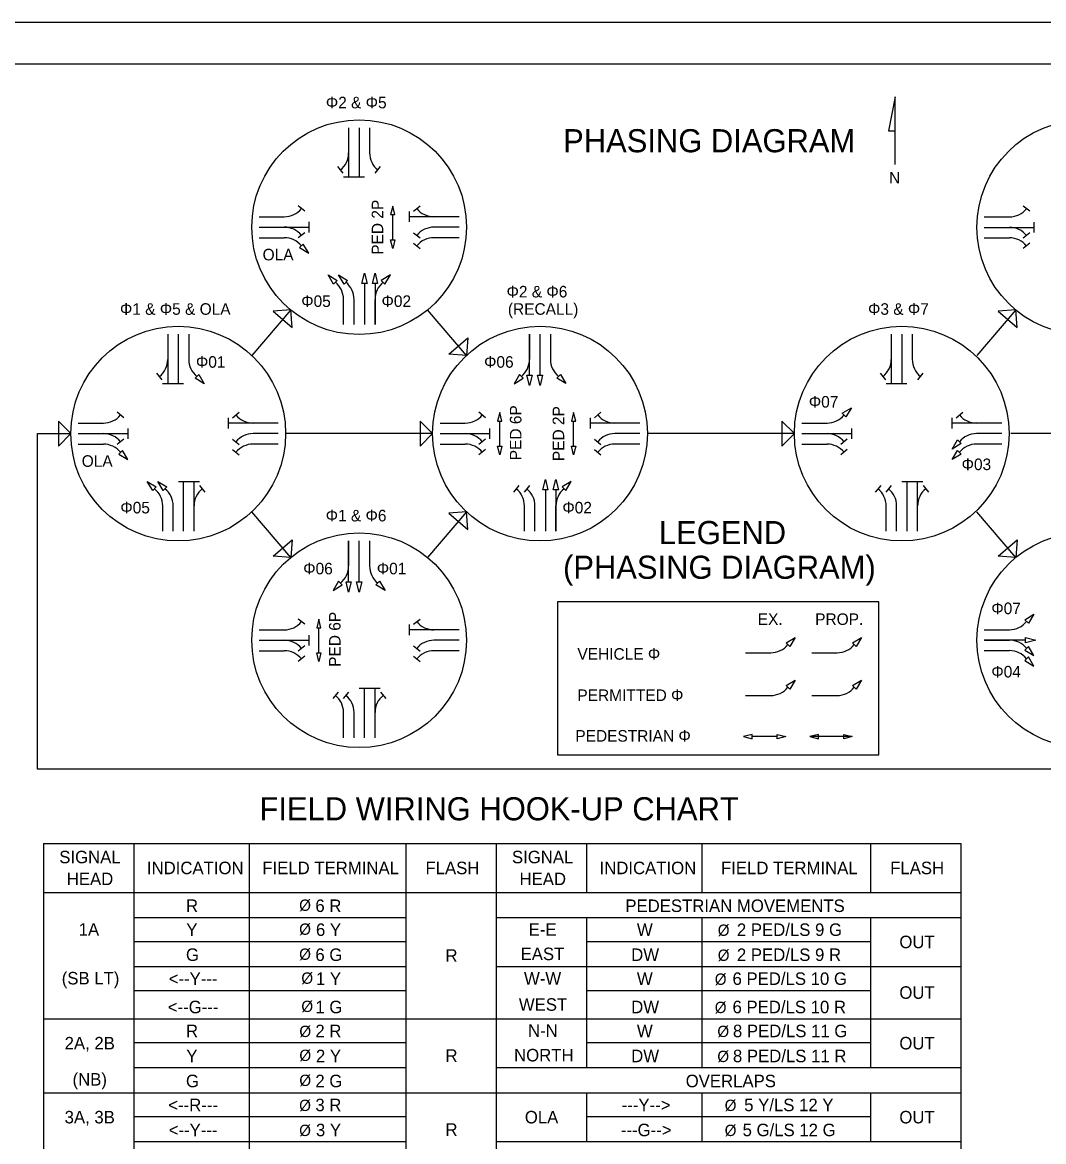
# Model space of a CAD drawing. Extents: x 0 to 34, y 0 to 22.
# Drawn here: x 14.75 to 27.11, y 8.45 to 22 of the extents above; entities that cross this region are included whole.
import ezdxf

# ---------------------------------------------------------------- set-up
doc = ezdxf.new("R2010")
doc.units = 0
for name, color, linetype in [('SG_P_Text', 7, 'Continuous'), ('SH_Border', 7, 'Continuous'), ('SH_Cut_Line', 7, 'Continuous'), ('SH_Text', 7, 'Continuous')]:
    doc.layers.add(name, color=color, linetype=linetype)

msp = doc.modelspace()

# ---------------------------------------------------------------- linework, layer by layer
at = {"layer": 'SG_P_Text'}
for p, q in [((18.699, 20.725), (18.699, 20.124)), ((18.699, 20.725), (18.699, 20.419)), ((18.826, 20.725), (18.826, 20.124)), ((18.952, 20.725), (18.952, 20.42)), ((18.632, 20.173), (18.568, 20.253)), ((19.019, 20.173), (19.083, 20.253)), ((18.762, 20.124), (18.635, 20.124)), ((18.889, 20.124), (18.762, 20.124)), ((18.167, 19.713), (18.087, 19.777)), ((19.233, 19.367), (19.233, 19.672)), ((19.436, 19.583), (19.436, 19.71)), ((19.484, 19.713), (19.564, 19.777)), ((26.947, 19.712), (26.868, 19.776)), ((17.615, 19.646), (17.92, 19.646)), ((17.615, 19.52), (18.215, 19.52)), ((17.615, 19.52), (17.92, 19.52)), ((18.215, 19.583), (18.215, 19.456)), ((20.036, 19.646), (19.436, 19.646)), ((20.036, 19.646), (19.731, 19.646)), ((20.036, 19.52), (19.731, 19.52)), ((26.395, 19.645), (26.701, 19.645)), ((26.395, 19.518), (26.996, 19.518)), ((26.395, 19.518), (26.701, 19.518)), ((26.996, 19.582), (26.996, 19.455)), ((17.615, 19.393), (17.92, 19.393)), ((18.167, 19.453), (18.087, 19.389)), ((19.484, 19.453), (19.564, 19.389)), ((20.036, 19.393), (19.731, 19.393)), ((26.395, 19.392), (26.701, 19.392)), ((26.947, 19.451), (26.868, 19.387)), ((19.484, 19.326), (19.564, 19.262)), ((26.947, 19.325), (26.868, 19.261)), ((18.891, 18.838), (18.891, 18.34)), ((19.018, 18.838), (19.018, 18.34)), ((18.637, 18.34), (18.637, 18.646)), ((18.764, 18.34), (18.764, 18.646)), ((19.018, 18.34), (19.018, 18.646)), ((17.997, 18.518), (17.526, 17.966)), ((20.125, 17.967), (19.654, 18.519)), ((26.777, 18.518), (26.307, 17.967)), ((16.509, 18.225), (16.509, 17.624)), ((16.509, 18.225), (16.509, 17.919)), ((16.635, 18.225), (16.635, 17.624)), ((16.762, 18.225), (16.762, 17.919)), ((20.889, 17.727), (20.889, 18.225)), ((20.889, 18.225), (20.889, 17.919)), ((21.016, 17.727), (21.016, 18.225)), ((21.142, 18.225), (21.142, 17.92)), ((25.269, 18.225), (25.269, 17.624)), ((25.269, 18.225), (25.269, 17.919)), ((25.396, 18.225), (25.396, 17.624)), ((25.523, 18.225), (25.523, 17.92)), ((16.442, 17.673), (16.378, 17.753)), ((16.572, 17.624), (16.445, 17.624)), ((16.699, 17.624), (16.572, 17.624)), ((25.202, 17.673), (25.138, 17.753)), ((25.332, 17.624), (25.206, 17.624)), ((25.459, 17.624), (25.332, 17.624)), ((25.59, 17.673), (25.654, 17.753)), ((15.977, 17.213), (15.897, 17.278)), ((17.294, 17.213), (17.374, 17.278)), ((20.357, 17.213), (20.277, 17.278)), ((21.674, 17.213), (21.754, 17.278)), ((26.055, 17.213), (26.134, 17.278)), ((15.425, 17.147), (15.73, 17.147)), ((16.025, 17.083), (16.025, 16.956)), ((17.245, 17.083), (17.245, 17.21)), ((17.846, 17.147), (17.245, 17.147)), ((17.846, 17.147), (17.541, 17.147)), ((19.805, 17.147), (20.111, 17.147)), ((20.406, 17.083), (20.406, 16.956)), ((20.528, 16.867), (20.528, 17.172)), ((21.423, 16.867), (21.423, 17.172)), ((21.626, 17.083), (21.626, 17.21)), ((22.226, 17.147), (21.626, 17.147)), ((22.226, 17.147), (21.921, 17.147)), ((24.185, 17.147), (24.491, 17.147)), ((24.786, 17.083), (24.786, 16.956)), ((26.006, 17.083), (26.006, 17.21)), ((26.606, 17.147), (26.006, 17.147)), ((26.606, 17.147), (26.301, 17.147)), ((15.425, 17.02), (16.025, 17.02)), ((15.425, 17.02), (15.73, 17.02)), ((15.977, 16.953), (15.897, 16.889)), ((17.294, 16.953), (17.374, 16.889)), ((17.846, 17.02), (17.541, 17.02)), ((19.716, 17.02), (17.935, 17.02)), ((19.805, 17.02), (20.406, 17.02)), ((19.805, 17.02), (20.111, 17.02)), ((20.357, 16.953), (20.277, 16.889)), ((21.674, 16.953), (21.754, 16.889)), ((22.226, 17.02), (21.921, 17.02)), ((24.096, 17.02), (22.315, 17.02)), ((24.185, 17.02), (24.786, 17.02)), ((24.185, 17.02), (24.491, 17.02)), ((24.737, 16.953), (24.657, 16.889)), ((26.606, 17.02), (26.301, 17.02)), ((28.496, 17.02), (26.716, 17.02)), ((15.425, 16.893), (15.73, 16.893)), ((17.294, 16.826), (17.374, 16.762)), ((17.846, 16.893), (17.541, 16.893)), ((19.805, 16.893), (20.111, 16.893)), ((20.357, 16.826), (20.277, 16.762)), ((21.674, 16.826), (21.754, 16.762)), ((22.226, 16.893), (21.921, 16.893)), ((24.185, 16.893), (24.491, 16.893)), ((24.737, 16.826), (24.657, 16.762)), ((26.606, 16.893), (26.301, 16.893)), ((16.637, 16.441), (16.764, 16.441)), ((16.701, 15.84), (16.701, 16.441)), ((16.764, 16.441), (16.891, 16.441)), ((16.827, 15.84), (16.827, 16.441)), ((25.398, 16.441), (25.525, 16.441)), ((25.461, 15.84), (25.461, 16.441)), ((25.525, 16.441), (25.651, 16.441)), ((25.588, 15.84), (25.588, 16.441)), ((16.894, 16.392), (16.958, 16.313)), ((20.76, 16.392), (20.696, 16.313)), ((20.887, 16.392), (20.823, 16.313)), ((21.081, 16.338), (21.081, 15.84)), ((21.208, 16.338), (21.208, 15.84)), ((25.141, 16.392), (25.076, 16.313)), ((25.267, 16.392), (25.203, 16.313)), ((25.655, 16.392), (25.719, 16.313)), ((16.447, 15.84), (16.447, 16.146)), ((16.574, 15.84), (16.574, 16.146)), ((16.827, 15.84), (16.827, 16.146)), ((20.827, 15.84), (20.827, 16.146)), ((20.954, 15.84), (20.954, 16.146)), ((21.208, 15.84), (21.208, 16.146)), ((25.207, 15.84), (25.207, 16.146)), ((25.334, 15.84), (25.334, 16.146)), ((25.588, 15.84), (25.588, 16.146)), ((17.998, 15.52), (17.526, 16.073)), ((20.125, 16.073), (19.653, 15.52)), ((26.778, 15.521), (26.307, 16.072)), ((18.699, 15.225), (18.699, 15.723)), ((18.699, 15.723), (18.699, 15.417)), ((18.826, 15.225), (18.826, 15.723)), ((18.952, 15.723), (18.952, 15.417)), ((18.167, 14.711), (18.087, 14.775)), ((19.484, 14.711), (19.564, 14.775)), ((17.615, 14.644), (17.92, 14.644)), ((18.338, 14.365), (18.338, 14.67)), ((19.436, 14.581), (19.436, 14.708)), ((20.036, 14.644), (19.436, 14.644)), ((20.036, 14.644), (19.731, 14.644)), ((26.395, 14.646), (26.701, 14.646)), ((17.615, 14.518), (18.215, 14.518)), ((17.615, 14.518), (17.92, 14.518)), ((18.215, 14.581), (18.215, 14.454)), ((20.036, 14.518), (19.731, 14.518)), ((26.893, 14.519), (26.395, 14.519)), ((26.396, 14.519), (26.701, 14.519)), ((17.615, 14.391), (17.92, 14.391)), ((18.167, 14.451), (18.087, 14.387)), ((19.484, 14.451), (19.564, 14.387)), ((20.036, 14.391), (19.731, 14.391)), ((26.395, 14.392), (26.701, 14.392)), ((18.167, 14.324), (18.087, 14.26)), ((19.484, 14.324), (19.564, 14.26)), ((23.505, 14.366), (23.81, 14.366)), ((24.308, 14.366), (24.614, 14.366)), ((18.57, 13.89), (18.506, 13.811)), ((18.697, 13.89), (18.633, 13.811)), ((18.827, 13.939), (18.954, 13.939)), ((18.891, 13.338), (18.891, 13.939)), ((18.954, 13.939), (19.081, 13.939)), ((19.018, 13.338), (19.018, 13.939)), ((19.085, 13.89), (19.149, 13.811)), ((23.505, 13.849), (23.81, 13.849)), ((24.308, 13.849), (24.614, 13.849)), ((18.637, 13.338), (18.637, 13.644)), ((18.764, 13.338), (18.764, 13.644)), ((19.018, 13.338), (19.018, 13.644)), ((23.889, 13.351), (23.584, 13.351)), ((24.797, 13.351), (24.284, 13.351))]:
    msp.add_line(p, q, dxfattribs=at)
for points in [[(19.259, 19.672), (19.233, 19.776), (19.207, 19.672)], [(18.105, 19.272), (18.215, 19.206), (18.149, 19.316)], [(19.259, 19.367), (19.233, 19.263), (19.207, 19.367)], [(18.516, 18.83), (18.45, 18.941), (18.56, 18.874)], [(18.643, 18.83), (18.577, 18.941), (18.687, 18.874)], [(18.859, 18.838), (18.891, 18.963), (18.922, 18.838)], [(18.986, 18.838), (19.018, 18.963), (19.049, 18.838)], [(19.139, 18.83), (19.205, 18.941), (19.094, 18.874)], [(17.997, 18.518), (17.783, 18.502), (18.014, 18.305)], [(26.777, 18.518), (26.563, 18.501), (26.793, 18.304)], [(20.125, 17.967), (19.912, 17.983), (20.142, 18.18)], [(16.883, 17.735), (16.949, 17.624), (16.839, 17.691)], [(20.768, 17.735), (20.702, 17.624), (20.812, 17.691)], [(20.92, 17.727), (20.889, 17.602), (20.858, 17.727)], [(21.047, 17.727), (21.016, 17.602), (20.984, 17.727)], [(21.263, 17.735), (21.33, 17.625), (21.219, 17.691)], [(20.554, 17.172), (20.528, 17.276), (20.502, 17.172)], [(21.449, 17.172), (21.423, 17.276), (21.397, 17.172)], [(24.675, 17.268), (24.786, 17.334), (24.719, 17.223)], [(15.336, 17.02), (15.184, 17.171), (15.184, 16.868)], [(19.716, 17.02), (19.565, 17.171), (19.564, 16.868)], [(24.096, 17.02), (23.945, 17.171), (23.945, 16.868)], [(26.117, 16.899), (26.006, 16.833), (26.072, 16.943)], [(15.915, 16.772), (16.025, 16.706), (15.959, 16.816)], [(20.554, 16.867), (20.528, 16.763), (20.502, 16.867)], [(21.449, 16.867), (21.423, 16.763), (21.397, 16.867)], [(26.117, 16.772), (26.006, 16.706), (26.072, 16.816)], [(16.326, 16.33), (16.26, 16.441), (16.37, 16.375)], [(16.453, 16.33), (16.387, 16.441), (16.497, 16.375)], [(21.05, 16.338), (21.081, 16.463), (21.112, 16.338)], [(21.176, 16.338), (21.208, 16.463), (21.239, 16.338)], [(21.329, 16.33), (21.395, 16.441), (21.284, 16.375)], [(20.125, 16.073), (19.912, 16.056), (20.142, 15.859)], [(17.998, 15.52), (17.784, 15.536), (18.015, 15.733)], [(26.778, 15.521), (26.564, 15.537), (26.795, 15.734)], [(18.578, 15.233), (18.512, 15.122), (18.622, 15.189)], [(18.73, 15.225), (18.699, 15.1), (18.667, 15.225)], [(18.857, 15.225), (18.826, 15.1), (18.794, 15.225)], [(19.073, 15.233), (19.14, 15.122), (19.029, 15.189)], [(25.12, 14.982), (21.228, 14.982), (21.228, 13.129), (25.12, 13.129)], [(18.364, 14.67), (18.338, 14.774), (18.312, 14.67)], [(26.885, 14.767), (26.996, 14.833), (26.929, 14.723)], [(23.995, 14.487), (24.105, 14.553), (24.039, 14.443)], [(24.798, 14.487), (24.909, 14.553), (24.843, 14.443)], [(26.893, 14.55), (27.018, 14.519), (26.893, 14.488)], [(26.886, 14.398), (26.996, 14.332), (26.93, 14.442)], [(18.364, 14.365), (18.338, 14.261), (18.312, 14.365)], [(26.885, 14.271), (26.996, 14.205), (26.93, 14.316)], [(23.995, 13.97), (24.105, 14.036), (24.039, 13.926)], [(24.798, 13.97), (24.909, 14.036), (24.843, 13.926)], [(23.584, 13.377), (23.48, 13.351), (23.584, 13.325)], [(23.889, 13.377), (23.994, 13.351), (23.889, 13.325)], [(24.388, 13.377), (24.284, 13.351), (24.388, 13.325)], [(24.693, 13.377), (24.797, 13.351), (24.693, 13.325)]]:
    msp.add_lwpolyline(points, close=True, dxfattribs=at)
msp.add_lwpolyline([(31.096, 17.02), (31.502, 17.02), (31.502, 12.958), (15.336, 12.958), (14.93, 12.958), (14.93, 17.02), (15.336, 17.02)], dxfattribs=at)
for centre in [(18.826, 19.52), (27.606, 19.518), (16.635, 17.02), (21.016, 17.02), (25.396, 17.02), (18.826, 14.518), (27.606, 14.519)]:
    msp.add_circle(centre, 1.3, dxfattribs=at)
for centre, start, end in [((18.434, 20.419), 308.7993, 0), ((19.217, 20.42), 180, 231.2007), ((17.92, 19.911), 270, 321.2007), ((19.731, 19.911), 218.7993, 270), ((26.701, 19.91), 270, 321.2007), ((17.92, 19.255), 38.7993, 90), ((19.731, 19.255), 90, 141.2007), ((26.701, 19.253), 38.7993, 90), ((17.92, 19.128), 38.7993, 90), ((19.731, 19.128), 90, 141.2007), ((26.701, 19.126), 38.7993, 90), ((18.372, 18.646), 360, 51.2007), ((18.499, 18.646), 360, 51.2007), ((19.283, 18.646), 128.8122, 180.0129), ((16.244, 17.919), 308.7993, 0), ((17.027, 17.919), 180, 231.2007), ((20.624, 17.919), 308.8122, 0.0129), ((21.407, 17.92), 179.9871, 231.1878), ((25.004, 17.919), 308.7993, 0), ((25.788, 17.92), 180, 231.2007), ((15.73, 17.412), 270, 321.2007), ((17.541, 17.412), 218.7993, 270), ((20.111, 17.412), 270, 321.2007), ((21.921, 17.412), 218.7993, 270), ((24.491, 17.412), 270, 321.2007), ((26.301, 17.412), 218.7993, 270), ((15.73, 16.755), 38.7993, 90), ((17.541, 16.755), 90, 141.2007), ((20.111, 16.755), 38.7993, 90), ((21.921, 16.755), 90, 141.2007), ((24.491, 16.755), 38.7993, 90), ((26.301, 16.755), 90, 141.2007), ((15.73, 16.628), 38.7993, 90), ((17.541, 16.628), 90, 141.2007), ((20.111, 16.628), 38.7993, 90), ((21.921, 16.628), 90, 141.2007), ((24.491, 16.628), 38.7993, 90), ((26.301, 16.628), 90, 141.2007), ((16.182, 16.146), 360, 51.2007), ((16.309, 16.146), 360, 51.2007), ((17.092, 16.146), 128.7993, 180), ((20.562, 16.146), 360, 51.2007), ((20.689, 16.146), 360, 51.2007), ((21.473, 16.146), 128.8122, 180.0129), ((24.942, 16.146), 360, 51.2007), ((25.069, 16.146), 360, 51.2007), ((25.853, 16.146), 128.7993, 180), ((18.434, 15.417), 308.8122, 0.0129), ((19.217, 15.417), 180, 231.2007), ((17.92, 14.909), 270, 321.2007), ((19.731, 14.909), 218.7993, 270), ((26.701, 14.911), 270, 321.2007), ((17.92, 14.253), 38.7993, 90), ((19.731, 14.253), 90, 141.2007), ((26.701, 14.254), 38.8122, 90.0129), ((17.92, 14.126), 38.7993, 90), ((19.731, 14.126), 90, 141.2007), ((23.81, 14.631), 270.0129, 321.2136), ((24.614, 14.631), 270.0129, 321.2136), ((26.701, 14.127), 38.8122, 90.0129), ((18.372, 13.644), 360, 51.2007), ((18.499, 13.644), 360, 51.2007), ((19.283, 13.644), 128.7993, 180), ((23.81, 14.114), 270, 321.2007), ((24.614, 14.114), 270, 321.2007)]:
    msp.add_arc(centre, 0.265, start, end, dxfattribs=at)
at = {"layer": 'SH_Border'}
msp.add_lwpolyline([(1.5, 21.5), (33.5, 21.5), (33.5, 0.5), (1.5, 0.5)], close=True, dxfattribs=at)
at = {"layer": 'SH_Cut_Line'}
msp.add_lwpolyline([(0, 0), (34, 0), (34, 22), (0, 22)], close=True, dxfattribs=at)
at = {"layer": 'SH_Text'}
for p, q in [((25.317, 20.278), (25.317, 21.098)), ((15.005, 12.057), (20.486, 12.057)), ((15.005, 12.057), (15.005, 11.161)), ((16.099, 12.057), (16.099, 11.161)), ((17.495, 12.057), (17.495, 11.161)), ((19.393, 12.057), (19.393, 11.161)), ((20.486, 12.057), (26.113, 12.057)), ((20.486, 12.057), (20.486, 11.161)), ((21.58, 12.057), (21.58, 11.464)), ((22.977, 12.057), (22.977, 11.464)), ((25.019, 12.057), (25.019, 11.464)), ((26.113, 12.057), (26.113, 11.161)), ((15.005, 11.464), (20.486, 11.464)), ((20.486, 11.464), (26.113, 11.464)), ((15.005, 11.161), (15.005, 9.039)), ((16.099, 11.161), (19.393, 11.161)), ((16.099, 11.161), (16.099, 9.039)), ((17.495, 11.161), (17.495, 9.039)), ((19.393, 11.161), (19.393, 9.039)), ((20.486, 11.161), (26.113, 11.161)), ((20.486, 11.161), (20.486, 9.039)), ((21.58, 11.161), (21.58, 9.342)), ((22.977, 11.161), (22.977, 9.342)), ((25.019, 11.161), (25.019, 9.342)), ((26.113, 11.161), (26.113, 9.039)), ((16.099, 10.871), (19.393, 10.871)), ((21.58, 10.871), (25.019, 10.871)), ((16.099, 10.568), (19.393, 10.568)), ((20.486, 10.568), (26.113, 10.568)), ((16.099, 10.278), (19.393, 10.278)), ((21.58, 10.278), (25.019, 10.278)), ((15.005, 9.935), (20.486, 9.935)), ((20.486, 9.935), (26.113, 9.935)), ((16.099, 9.646), (19.393, 9.646)), ((21.58, 9.646), (25.019, 9.646)), ((16.099, 9.342), (19.393, 9.342)), ((20.486, 9.342), (26.113, 9.342)), ((15.005, 9.039), (20.486, 9.039)), ((15.005, 9.039), (15.005, 8.75)), ((16.099, 9.039), (16.099, 8.75)), ((17.495, 9.039), (17.495, 8.75)), ((19.393, 9.039), (19.393, 8.75)), ((20.486, 9.039), (26.113, 9.039)), ((20.486, 9.039), (20.486, 8.75)), ((21.58, 9.039), (21.58, 8.75)), ((22.977, 9.039), (22.977, 8.75)), ((25.019, 9.039), (25.019, 8.75)), ((26.113, 9.039), (26.113, 8.75)), ((15.005, 8.75), (15.005, 8.446)), ((16.099, 8.75), (19.393, 8.75)), ((16.099, 8.75), (16.099, 8.446)), ((17.495, 8.75), (17.495, 8.446)), ((19.393, 8.75), (19.393, 8.446)), ((20.486, 8.75), (20.486, 8.446)), ((21.58, 8.75), (25.019, 8.75)), ((21.58, 8.75), (21.58, 8.446)), ((22.977, 8.75), (22.977, 8.446)), ((25.019, 8.75), (25.019, 8.446)), ((26.113, 8.75), (26.113, 8.446)), ((15.005, 8.446), (15.005, 8.143)), ((16.099, 8.446), (19.393, 8.446)), ((16.099, 8.446), (16.099, 8.143)), ((17.495, 8.446), (17.495, 8.143)), ((19.393, 8.446), (19.393, 8.143)), ((20.486, 8.446), (26.113, 8.446)), ((20.486, 8.446), (20.486, 8.143)), ((26.113, 8.446), (26.113, 8.143))]:
    msp.add_line(p, q, dxfattribs=at)
msp.add_lwpolyline([(25.317, 21.098), (25.235, 20.688), (25.317, 20.688)], close=True, dxfattribs=at)

# ---------------------------------------------------------------- texts
at = {"layer": 'SG_P_Text'}
for s, height, p in [('Φ2 & Φ5', 0.14, (18.423, 20.959)), ('PHASING DIAGRAM', 0.28, (21.296, 20.427)), ('OLA', 0.14, (17.657, 19.118)), ('Φ2 & Φ6', 0.14, (20.611, 18.669)), ('Φ1 & Φ5 & OLA', 0.14, (15.93, 18.459)), ('Φ05', 0.14, (18.125, 18.554)), ('Φ02', 0.14, (19.097, 18.554)), ('(RECALL)', 0.14, (20.627, 18.459)), ('Φ3 & Φ7', 0.14, (24.988, 18.459)), ('Φ01', 0.14, (16.85, 17.818)), ('Φ06', 0.14, (20.339, 17.818)), ('Φ07', 0.14, (24.271, 17.335)), ('OLA', 0.14, (15.467, 16.618)), ('Φ03', 0.14, (26.121, 16.578)), ('Φ05', 0.14, (15.935, 16.054)), ('Φ02', 0.14, (21.287, 16.054)), ('Φ1 & Φ6', 0.14, (18.421, 15.957)), ('Φ06', 0.14, (18.149, 15.316)), ('Φ01', 0.14, (19.04, 15.316)), ('Φ07', 0.14, (26.481, 14.834)), ('EX.', 0.14, (23.652, 14.703)), ('PROP.', 0.14, (24.348, 14.703)), ('VEHICLE Φ', 0.14, (21.469, 14.282)), ('Φ04', 0.14, (26.481, 14.067)), ('PERMITTED Φ', 0.14, (21.469, 13.782)), ('PEDESTRIAN Φ', 0.14, (21.444, 13.29)), ('FIELD WIRING HOOK-UP CHART', 0.28, (17.619, 12.337))]:
    msp.add_text(s, height=height, dxfattribs=at).set_placement(p)
for s, p in [('PED 2P', (19.118, 19.186)), ('PED 6P', (20.791, 16.698)), ('PED 2P', (21.309, 16.687)), ('PED 6P', (18.601, 14.196))]:
    msp.add_text(s, height=0.14, rotation=90, dxfattribs=at).set_placement(p)
at = {"layer": 'SH_Text'}
for s, height, p in [('N', 0.14, (25.242, 20.05)), ('LEGEND ', 0.28, (22.456, 15.682)), ('(PHASING DIAGRAM)', 0.28, (21.295, 15.262)), ('SIGNAL ', 0.1515, (15.195, 11.817)), ('SIGNAL ', 0.1515, (20.676, 11.817)), ('INDICATION', 0.1515, (16.256, 11.685)), ('FIELD TERMINAL', 0.15153, (17.653, 11.685)), ('FLASH', 0.1515, (19.629, 11.685)), ('INDICATION', 0.1515, (21.737, 11.685)), ('FIELD TERMINAL', 0.15153, (23.207, 11.685)), ('FLASH', 0.1515, (25.256, 11.685)), ('HEAD', 0.1515, (15.286, 11.552)), ('HEAD', 0.1515, (20.768, 11.552)), ('R', 0.152, (16.729, 11.227)), ('Ø', 0.137, (18.1, 11.241)), ('6 R', 0.1515, (18.296, 11.227)), ('PEDESTRIAN MOVEMENTS', 0.15153, (22.049, 11.227)), ('1A', 0.1515, (15.43, 10.94)), ('Y', 0.152, (16.733, 10.937)), ('Ø', 0.137, (18.1, 10.951)), ('6 Y', 0.1515, (18.303, 10.937)), ('E-E', 0.1515, (20.879, 10.94)), ('W', 0.152, (22.189, 10.937)), ('Ø', 0.137, (23.168, 10.938)), ('2 PED/LS 9 G', 0.15153, (23.4, 10.937)), ('OUT', 0.1515, (25.367, 10.789)), ('G', 0.152, (16.729, 10.634)), ('Ø', 0.137, (18.1, 10.648)), ('6 G', 0.1515, (18.296, 10.634)), ('R', 0.152, (19.871, 10.624)), ('EAST', 0.1515, (20.781, 10.644)), ('DW', 0.1515, (22.12, 10.634)), ('Ø', 0.137, (23.168, 10.635)), ('2 PED/LS 9 R', 0.15153, (23.4, 10.634)), ('(SB LT)', 0.1515, (15.225, 10.35)), ('<--Y---', 0.1515, (16.52, 10.344)), ('Ø', 0.137, (18.126, 10.358)), ('1 Y', 0.1515, (18.303, 10.344)), ('W-W', 0.1515, (20.822, 10.347)), ('W', 0.152, (22.189, 10.344)), ('Ø', 0.137, (23.132, 10.345)), ('6 PED/LS 10 G', 0.15153, (23.347, 10.344)), ('OUT', 0.1515, (25.367, 10.176)), ('WEST', 0.1515, (20.76, 10.031)), ('<--G---', 0.1515, (16.509, 10.001)), ('Ø', 0.137, (18.126, 10.016)), ('1 G', 0.1515, (18.296, 10.001)), ('DW', 0.1515, (22.12, 10.001)), ('Ø', 0.137, (23.132, 10.003)), ('6 PED/LS 10 R', 0.15153, (23.347, 10.001)), ('R', 0.152, (16.729, 9.711)), ('Ø', 0.137, (18.102, 9.713)), ('2 R', 0.1515, (18.296, 9.711)), ('N-N', 0.1515, (20.871, 9.715)), ('W', 0.152, (22.189, 9.711)), ('Ø', 0.137, (23.163, 9.713)), ('8 PED/LS 11 G', 0.15153, (23.352, 9.711)), ('2A, 2B', 0.1515, (15.26, 9.563)), ('OUT', 0.1515, (25.367, 9.563)), ('Y', 0.152, (16.733, 9.408)), ('Ø', 0.137, (18.102, 9.423)), ('2 Y', 0.1515, (18.303, 9.408)), ('R', 0.152, (19.871, 9.412)), ('NORTH', 0.1515, (20.702, 9.418)), ('DW', 0.1515, (22.12, 9.408)), ('Ø', 0.137, (23.163, 9.41)), ('8 PED/LS 11 R', 0.15153, (23.352, 9.408)), ('(NB)', 0.1515, (15.356, 9.125)), ('G', 0.152, (16.729, 9.105)), ('Ø', 0.137, (18.102, 9.12)), ('2 G', 0.1515, (18.296, 9.105)), ('OVERLAPS', 0.1515, (22.78, 9.105)), ('<--R---', 0.1515, (16.515, 8.815)), ('Ø', 0.137, (18.1, 8.817)), ('3 R', 0.1515, (18.296, 8.815)), ('---Y-->', 0.1515, (22.005, 8.815)), ('Ø', 0.137, (23.252, 8.817)), ('5 Y/LS 12 Y', 0.15153, (23.488, 8.815)), ('3A, 3B', 0.1515, (15.26, 8.667)), ('OLA', 0.1515, (20.832, 8.667)), ('OUT', 0.1515, (25.367, 8.667)), ('<--Y---', 0.1515, (16.52, 8.512)), ('Ø', 0.137, (18.1, 8.514)), ('3 Y', 0.1515, (18.303, 8.512)), ('R', 0.152, (19.871, 8.516)), ('---G-->', 0.1515, (21.995, 8.512)), ('Ø', 0.137, (23.252, 8.514)), ('5 G/LS 12 G', 0.15153, (23.469, 8.512))]:
    msp.add_text(s, height=height, dxfattribs=at).set_placement(p)

doc.saveas('drawing.dxf')
